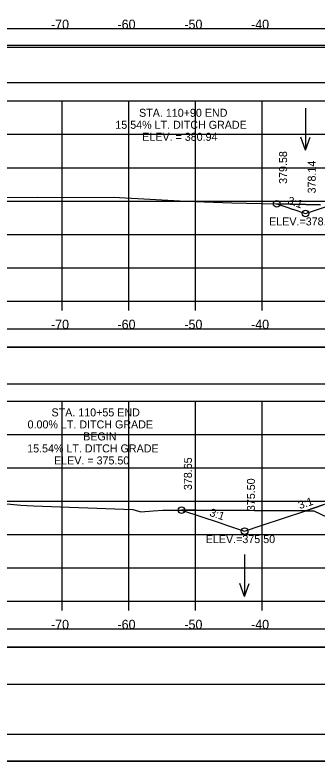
# Model space of a CAD drawing. Extents: x -37291014 to -37290680, y -936053 to -933067.
# Drawn here: x -37290920.2 to -37290874.9, y -933919.9 to -933808 of the extents above; entities that cross this region are included whole.
import ezdxf

# ---------------------------------------------------------------- set-up
doc = ezdxf.new("R2010")
doc.units = 0
for name, color, linetype in [('Default', 7, 'Continuous'), ('R_Axis', 7, 'Continuous'), ('R_Axis Annot', 7, 'Continuous'), ('R_Border', 7, 'Continuous'), ('R_Contours', 7, 'Continuous'), ('R_Exist Surface', 7, 'Continuous'), ('R_Fin Surface', 7, 'Continuous'), ('R_Grid', 7, 'Continuous'), ('R_No Plot', 7, 'Continuous'), ('R_Water Annot', 7, 'Continuous'), ('R_Xsect Elev', 7, 'Continuous'), ('R_Xsect Slope', 7, 'Continuous')]:
    doc.layers.add(name, color=color, linetype=linetype)

msp = doc.modelspace()

# ---------------------------------------------------------------- linework, layer by layer
at = {"layer": 'Default'}
for points in [[(-37290992.48, -933812.85), (-37290693.72, -933812.85), (-37290693.72, -933810.14), (-37290992.48, -933810.14)], [(-37290992.31, -933818.16), (-37290693.55, -933818.16), (-37290693.55, -933812.64), (-37290992.31, -933812.64)], [(-37290992.48, -933857.85), (-37290693.72, -933857.85), (-37290693.72, -933855.14), (-37290992.48, -933855.14)], [(-37290992.48, -933863.37), (-37290693.72, -933863.37), (-37290693.72, -933857.85), (-37290992.48, -933857.85)], [(-37290992.48, -933902.85), (-37290693.72, -933902.85), (-37290693.72, -933900.14), (-37290992.48, -933900.14)], [(-37290992.48, -933908.37), (-37290693.72, -933908.37), (-37290693.72, -933902.85), (-37290992.48, -933902.85)]]:
    msp.add_lwpolyline(points, close=True, dxfattribs=at)
at = {"layer": 'R_Axis'}
for p, q in [((-37290993.1, -933850.94), (-37290693.1, -933850.94)), ((-37290913.1, -933852.34), (-37290913.1, -933850.94)), ((-37290903.1, -933852.34), (-37290903.1, -933850.94)), ((-37290893.1, -933852.34), (-37290893.1, -933850.94)), ((-37290883.1, -933852.34), (-37290883.1, -933850.94)), ((-37290993.1, -933895.94), (-37290693.1, -933895.94)), ((-37290913.1, -933897.34), (-37290913.1, -933895.94)), ((-37290903.1, -933897.34), (-37290903.1, -933895.94)), ((-37290893.1, -933897.34), (-37290893.1, -933895.94)), ((-37290883.1, -933897.34), (-37290883.1, -933895.94))]:
    msp.add_line(p, q, dxfattribs=at)
at = {"layer": 'R_Border'}
msp.add_line((-37290684.92, -933915.94), (-37291001.1, -933915.94), dxfattribs=at)
at = {"layer": 'R_Contours'}
for p, q in [((-37290874.34, -933836.5), (-37290880.91, -933836.37)), ((-37290893.18, -933882.28), (-37290895.18, -933882.29)), ((-37290876.56, -933882.39), (-37290893.18, -933882.28))]:
    msp.add_line(p, q, dxfattribs=at)
for points in [[(-37290880.91, -933836.37), (-37290879.24, -933836.93), (-37290878.58, -933837.14), (-37290878.52, -933837.16), (-37290876.61, -933837.8), (-37290874.51, -933837.1), (-37290872.86, -933836.55)], [(-37290867.27, -933879.29), (-37290873.96, -933881.52), (-37290876.56, -933882.39)], [(-37290895.18, -933882.29), (-37290889.54, -933884.17), (-37290888.28, -933884.59), (-37290885.72, -933885.44), (-37290883.22, -933884.61), (-37290876.56, -933882.39)], [(-37290876.56, -933882.39), (-37290875.35, -933882.4), (-37290873.36, -933883.36)]]:
    msp.add_lwpolyline(points, dxfattribs=at)
at = {"layer": 'R_Exist Surface'}
for points in [[(-37290929.18, -933835.4), (-37290916.8, -933835.38), (-37290912.84, -933835.39), (-37290905.39, -933835.36), (-37290899.05, -933835.7), (-37290894.54, -933835.94), (-37290887.64, -933836.23), (-37290874.34, -933836.5)], [(-37290926.63, -933880.87), (-37290919.27, -933881.55), (-37290917.36, -933881.67), (-37290902.48, -933882.18), (-37290901.27, -933882.56), (-37290899.44, -933882.38), (-37290897.99, -933882.31), (-37290893.18, -933882.28), (-37290875.35, -933882.4), (-37290873.36, -933883.36)]]:
    msp.add_lwpolyline(points, dxfattribs=at)
at = {"layer": 'R_Fin Surface'}
for points in [[(-37290880.91, -933836.37), (-37290879.24, -933836.93), (-37290878.58, -933837.14), (-37290878.52, -933837.16), (-37290876.61, -933837.8), (-37290874.51, -933837.1)], [(-37290895.18, -933882.29), (-37290889.54, -933884.17), (-37290888.28, -933884.59), (-37290885.72, -933885.44), (-37290883.22, -933884.61), (-37290876.56, -933882.39), (-37290873.96, -933881.52)]]:
    msp.add_lwpolyline(points, dxfattribs=at)
at = {"layer": 'R_Grid'}
for p, q in [((-37290993.1, -933820.94), (-37290693.1, -933820.94)), ((-37290913.1, -933850.94), (-37290913.1, -933820.94)), ((-37290903.1, -933850.94), (-37290903.1, -933820.94)), ((-37290893.1, -933850.94), (-37290893.1, -933820.94)), ((-37290883.1, -933850.94), (-37290883.1, -933820.94)), ((-37290993.1, -933825.94), (-37290693.1, -933825.94)), ((-37290993.1, -933830.94), (-37290693.1, -933830.94)), ((-37290993.1, -933835.94), (-37290693.1, -933835.94)), ((-37290993.1, -933840.94), (-37290693.1, -933840.94)), ((-37290993.1, -933845.94), (-37290693.1, -933845.94)), ((-37290993.1, -933850.94), (-37290693.1, -933850.94)), ((-37290993.1, -933865.94), (-37290693.1, -933865.94)), ((-37290913.1, -933895.94), (-37290913.1, -933865.94)), ((-37290903.1, -933895.94), (-37290903.1, -933865.94)), ((-37290893.1, -933895.94), (-37290893.1, -933865.94)), ((-37290883.1, -933895.94), (-37290883.1, -933865.94)), ((-37290993.1, -933870.94), (-37290693.1, -933870.94)), ((-37290993.1, -933875.94), (-37290693.1, -933875.94)), ((-37290993.1, -933880.94), (-37290693.1, -933880.94)), ((-37290993.1, -933885.94), (-37290693.1, -933885.94)), ((-37290993.1, -933890.94), (-37290693.1, -933890.94)), ((-37290993.1, -933895.94), (-37290693.1, -933895.94))]:
    msp.add_line(p, q, dxfattribs=at)
at = {"layer": 'R_No Plot'}
msp.add_line((-37291013.5, -933919.92), (-37290680.17, -933919.92), dxfattribs=at)
for points in [[(-37291013.51, -933706.59), (-37290680.17, -933706.59), (-37290680.17, -933919.93), (-37291013.51, -933919.93)], [(-37290767.18, -933710.48), (-37290747.56, -933710.48), (-37290747.56, -933720.36), (-37290731.45, -933720.36), (-37290708.25, -933720.36), (-37290708.25, -933744.7), (-37290684.92, -933744.7), (-37290684.92, -933915.94), (-37291001.1, -933915.94), (-37291001.1, -933710.48)]]:
    msp.add_lwpolyline(points, close=True, dxfattribs=at)
for centre in [(-37290880.91, -933836.37), (-37290876.61, -933837.8), (-37290895.18, -933882.29), (-37290885.72, -933885.44)]:
    msp.add_circle(centre, 0.5, dxfattribs=at)
at = {"layer": 'R_Water Annot'}
for p, q in [((-37290876.61, -933822.03), (-37290876.61, -933828.31)), ((-37290876.61, -933828.31), (-37290877.31, -933826.39)), ((-37290876.61, -933828.31), (-37290875.91, -933826.39)), ((-37290885.72, -933888.96), (-37290885.72, -933895.24)), ((-37290885.72, -933895.24), (-37290886.42, -933893.32)), ((-37290885.72, -933895.24), (-37290885.02, -933893.32))]:
    msp.add_line(p, q, dxfattribs=at)

# ---------------------------------------------------------------- texts
at = {"layer": 'R_Axis Annot'}
for s, p in [('-70', (-37290914.76, -933810.14)), ('-60', (-37290904.79, -933810.14)), ('-50', (-37290894.76, -933810.14)), ('-40', (-37290884.76, -933810.14)), ('-70', (-37290914.76, -933855.14)), ('-60', (-37290904.79, -933855.14)), ('-50', (-37290894.76, -933855.14)), ('-40', (-37290884.76, -933855.14)), ('-70', (-37290914.76, -933900.14)), ('-60', (-37290904.79, -933900.14)), ('-50', (-37290894.76, -933900.14)), ('-40', (-37290884.76, -933900.14))]:
    msp.add_text(s, height=1.4, dxfattribs=at).set_placement(p)
at = {"layer": 'R_Xsect Elev'}
for s, p in [('STA. 110+90 END ', (-37290901.55, -933823.31)), ('15.54% LT. DITCH GRADE', (-37290905.11, -933825.11)), ('ELEV. = 380.94', (-37290901.08, -933826.91)), ('ELEV.=378.14', (-37290882.05, -933839.6)), ('STA. 110+55 END', (-37290914.68, -933868.24)), ('0.00% LT. DITCH GRADE', (-37290918.27, -933870.04)), ('BEGIN', (-37290909.93, -933871.84)), ('15.54% LT. DITCH GRADE', (-37290918.33, -933873.64)), ('ELEV. = 375.50', (-37290914.3, -933875.44)), ('ELEV.=375.50', (-37290891.55, -933887.24))]:
    msp.add_text(s, height=1.2, dxfattribs=at).set_placement(p)
for s, p in [('379.58', (-37290879.36, -933833.37)), ('378.14', (-37290875.06, -933834.8)), ('378.65', (-37290893.63, -933879.29)), ('375.50', (-37290884.17, -933882.44))]:
    msp.add_text(s, height=1.2, rotation=90, dxfattribs=at).set_placement(p)
at = {"layer": 'R_Xsect Slope'}
for rotation, p in [(341.5668, (-37290879.39, -933836.35)), (18.4332, (-37290877.45, -933882.16)), (341.5668, (-37290891.08, -933883.13))]:
    msp.add_text('3:1', height=1.2, rotation=rotation, dxfattribs=at).set_placement(p)

doc.saveas('drawing.dxf')
